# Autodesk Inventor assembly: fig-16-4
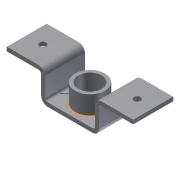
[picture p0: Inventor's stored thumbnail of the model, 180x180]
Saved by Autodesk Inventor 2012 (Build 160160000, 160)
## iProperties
Created: 2004-07
Part Number: fig-16-4
Document SubType Name: Weldment
Designer: CADCIM Technologies
Manufacturer: Standard
Standards Organization: Custom
Author: CADCIM Technologies
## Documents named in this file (3)
- C:\Users\CadCim\Documents\SAILESH\inventor-2011-fact-prt\c16-inv-2011-prt\c16_inv_2012_prt\fig-16-4.iam
- C:\Users\CadCim\Documents\SAILESH\inventor-2011-fact-prt\c16-inv-2011-prt\Bracket.ipt
- C:\Users\CadCim\Documents\SAILESH\inventor-2011-fact-prt\c16-inv-2011-prt\cylinder.ipt
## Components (2 placed, 2 different names)
1. Bracket:1 — Insert:1
2. cylinder:1 — Insert:1
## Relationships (1: Insert 1)
- Insert:1: Bracket:1 ↔ cylinder:1
